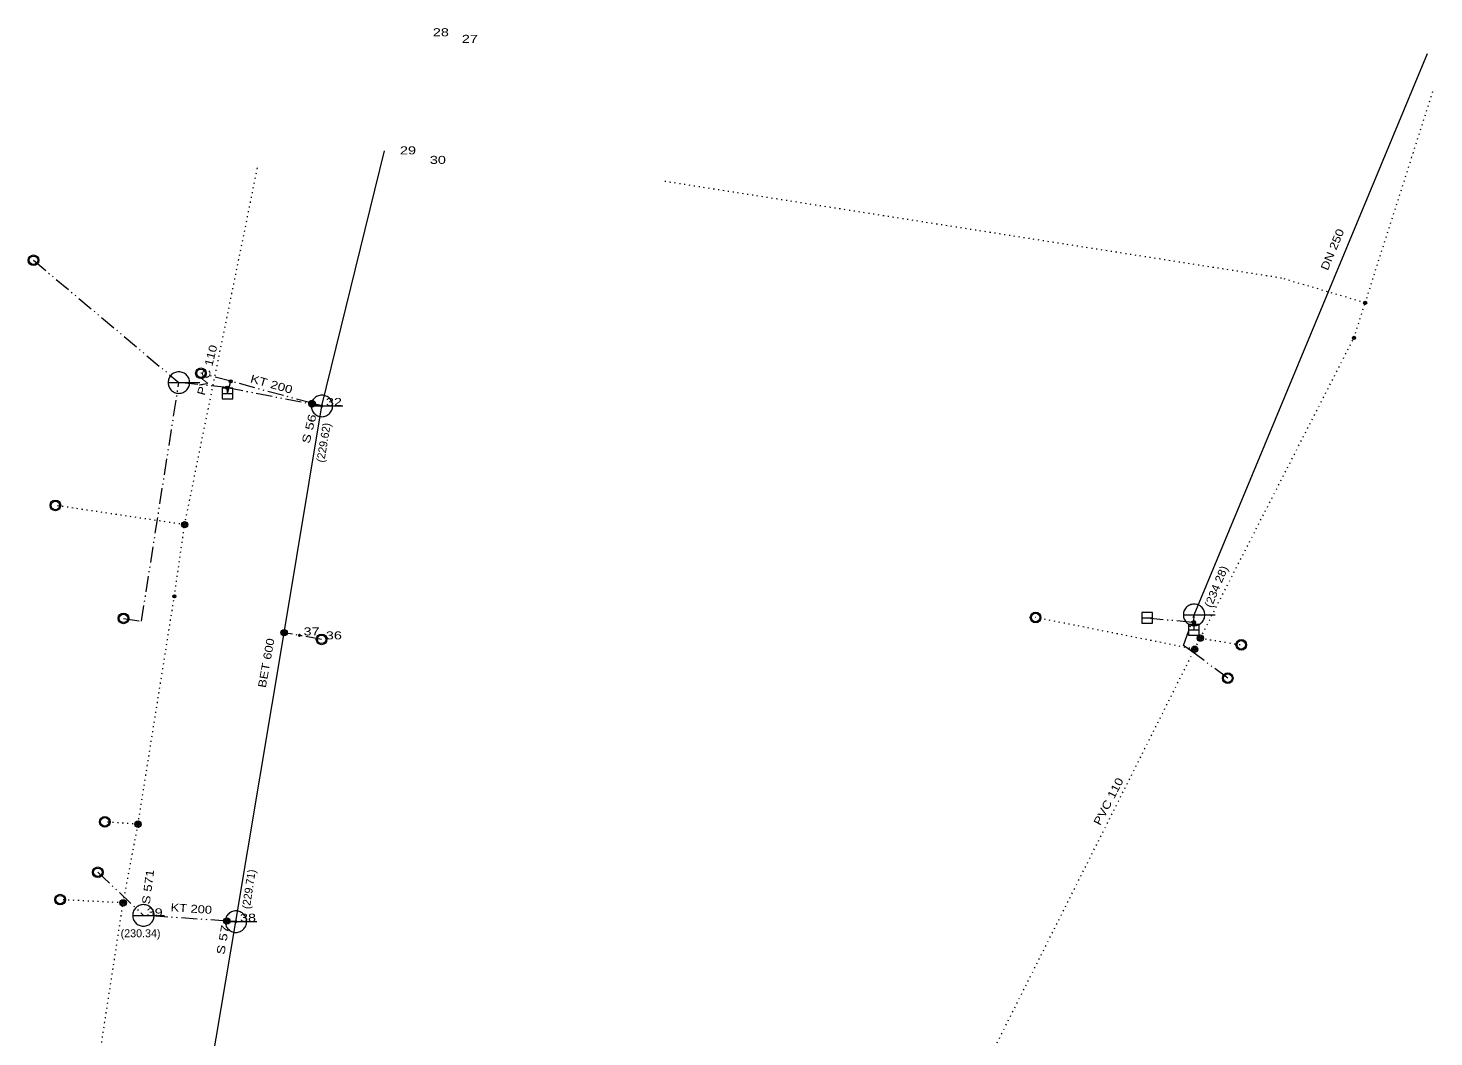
# Model space of a CAD drawing. Extents: x -648128 to -647962, y -1064951 to -1064761.
# Drawn here: x -648094.1 to -647962.3, y -1064855.2 to -1064760.6 of the extents above; entities that cross this region are included whole.
import ezdxf
from ezdxf.enums import TextEntityAlignment as Align

# ---------------------------------------------------------------- set-up
doc = ezdxf.new("R2010")
doc.units = 0
doc.header["$LTSCALE"] = 0.3
doc.header["$PDMODE"] = 32
doc.header["$PDSIZE"] = 0.15
doc.linetypes.add('DASH_DOUBLE_DOT', pattern=[9.2, 5, -1.2, 0.3, -1.2, 0.3, -1.2])
doc.linetypes.add('DOTTED', pattern=[1.5, 0.3, -1.2])
for name, color, linetype in [('1', 7, 'Continuous'), ('16', 7, 'Continuous'), ('18', 7, 'Continuous'), ('19', 7, 'Continuous'), ('2', 7, 'Continuous'), ('4', 7, 'Continuous')]:
    doc.layers.add(name, color=color, linetype=linetype)
for name, color, linetype, lineweight in [('10', 7, 'Continuous', 13), ('12', 7, 'Continuous', 13), ('30', 7, 'Continuous', 13), ('36', 7, 'DOTTED', 13), ('46', 7, 'Continuous', 13), ('5', 7, 'Continuous', 13), ('51', 7, 'DASH_DOUBLE_DOT', 13)]:
    doc.layers.add(name, color=color, linetype=linetype, lineweight=lineweight)

msp = doc.modelspace()

# ---------------------------------------------------------------- linework, layer by layer
at = {"layer": '1'}
for p in [(-648066.57, -1064796.08), (-648068.67, -1064817.6), (-648074.63, -1064844.44)]:
    msp.add_point(p, dxfattribs=at)
at = {"layer": '10'}
for p, q in [((-648075.92, -1064794.91), (-648074.92, -1064794.91)), ((-647989.7, -1064815.95), (-647988.7, -1064815.95)), ((-647985.35, -1064817.06), (-647984.35, -1064817.06))]:
    msp.add_line(p, q, dxfattribs=at)
for points in [[(-648075.92, -1064795.41), (-648074.92, -1064795.41), (-648074.92, -1064794.41), (-648075.92, -1064794.41)], [(-647989.7, -1064816.45), (-647988.7, -1064816.45), (-647988.7, -1064815.45), (-647989.7, -1064815.45)], [(-647985.35, -1064817.56), (-647984.35, -1064817.56), (-647984.35, -1064816.56), (-647985.35, -1064816.56)]]:
    msp.add_lwpolyline(points, close=True, dxfattribs=at)
at = {"layer": '12'}
for p, q in [((-648080.988, -1064793.89), (-648078.011, -1064793.89)), ((-648067.578, -1064796.08), (-648064.601, -1064796.08)), ((-647985.818, -1064815.67), (-647982.841, -1064815.67)), ((-648084.308, -1064843.85), (-648081.331, -1064843.85)), ((-648075.638, -1064844.44), (-648072.661, -1064844.44))]:
    msp.add_line(p, q, dxfattribs=at)
for points in [[(-648079.98, -1064792.882), (-648080.085, -1064792.888), (-648080.189, -1064792.904), (-648080.291, -1064792.931), (-648080.389, -1064792.969), (-648080.483, -1064793.017), (-648080.571, -1064793.074), (-648080.654, -1064793.141), (-648080.729, -1064793.216), (-648080.795, -1064793.298), (-648080.852, -1064793.385), (-648080.899, -1064793.48), (-648080.937, -1064793.579), (-648080.965, -1064793.68), (-648080.981, -1064793.785), (-648080.988, -1064793.89), (-648080.981, -1064793.995), (-648080.965, -1064794.1), (-648080.937, -1064794.202), (-648080.899, -1064794.3), (-648080.852, -1064794.393), (-648080.795, -1064794.483), (-648080.729, -1064794.565), (-648080.654, -1064794.639), (-648080.571, -1064794.705), (-648080.483, -1064794.763), (-648080.389, -1064794.811), (-648080.291, -1064794.849), (-648080.189, -1064794.876), (-648080.085, -1064794.892), (-648079.98, -1064794.898), (-648079.874, -1064794.892), (-648079.769, -1064794.876), (-648079.668, -1064794.849), (-648079.57, -1064794.811), (-648079.475, -1064794.763), (-648079.387, -1064794.705), (-648079.305, -1064794.639), (-648079.23, -1064794.565), (-648079.164, -1064794.483), (-648079.107, -1064794.393), (-648079.058, -1064794.3), (-648079.02, -1064794.202), (-648078.994, -1064794.1), (-648078.978, -1064793.995), (-648078.972, -1064793.89), (-648078.978, -1064793.785), (-648078.994, -1064793.68), (-648079.02, -1064793.579), (-648079.058, -1064793.48), (-648079.107, -1064793.385), (-648079.164, -1064793.298), (-648079.23, -1064793.216), (-648079.305, -1064793.141), (-648079.387, -1064793.074), (-648079.475, -1064793.017), (-648079.57, -1064792.969), (-648079.668, -1064792.931), (-648079.769, -1064792.904), (-648079.874, -1064792.888)], [(-648066.57, -1064795.072), (-648066.675, -1064795.078), (-648066.779, -1064795.094), (-648066.881, -1064795.121), (-648066.979, -1064795.159), (-648067.073, -1064795.207), (-648067.161, -1064795.264), (-648067.244, -1064795.331), (-648067.319, -1064795.406), (-648067.385, -1064795.488), (-648067.442, -1064795.575), (-648067.489, -1064795.67), (-648067.527, -1064795.769), (-648067.555, -1064795.87), (-648067.571, -1064795.975), (-648067.578, -1064796.08), (-648067.571, -1064796.185), (-648067.555, -1064796.29), (-648067.527, -1064796.392), (-648067.489, -1064796.49), (-648067.442, -1064796.583), (-648067.385, -1064796.673), (-648067.319, -1064796.755), (-648067.244, -1064796.829), (-648067.161, -1064796.895), (-648067.073, -1064796.953), (-648066.979, -1064797.001), (-648066.881, -1064797.039), (-648066.779, -1064797.066), (-648066.675, -1064797.082), (-648066.57, -1064797.088), (-648066.464, -1064797.082), (-648066.359, -1064797.066), (-648066.258, -1064797.039), (-648066.16, -1064797.001), (-648066.065, -1064796.953), (-648065.977, -1064796.895), (-648065.895, -1064796.829), (-648065.82, -1064796.755), (-648065.754, -1064796.673), (-648065.697, -1064796.583), (-648065.648, -1064796.49), (-648065.61, -1064796.392), (-648065.584, -1064796.29), (-648065.568, -1064796.185), (-648065.562, -1064796.08), (-648065.568, -1064795.975), (-648065.584, -1064795.87), (-648065.61, -1064795.769), (-648065.648, -1064795.67), (-648065.697, -1064795.575), (-648065.754, -1064795.488), (-648065.82, -1064795.406), (-648065.895, -1064795.331), (-648065.977, -1064795.264), (-648066.065, -1064795.207), (-648066.16, -1064795.159), (-648066.258, -1064795.121), (-648066.359, -1064795.094), (-648066.464, -1064795.078)], [(-647984.81, -1064814.662), (-647984.915, -1064814.668), (-647985.019, -1064814.684), (-647985.121, -1064814.711), (-647985.219, -1064814.749), (-647985.313, -1064814.797), (-647985.401, -1064814.854), (-647985.484, -1064814.921), (-647985.559, -1064814.996), (-647985.625, -1064815.078), (-647985.682, -1064815.165), (-647985.729, -1064815.26), (-647985.767, -1064815.359), (-647985.795, -1064815.46), (-647985.811, -1064815.565), (-647985.818, -1064815.67), (-647985.811, -1064815.775), (-647985.795, -1064815.88), (-647985.767, -1064815.982), (-647985.729, -1064816.08), (-647985.682, -1064816.173), (-647985.625, -1064816.263), (-647985.559, -1064816.345), (-647985.484, -1064816.419), (-647985.401, -1064816.485), (-647985.313, -1064816.543), (-647985.219, -1064816.591), (-647985.121, -1064816.629), (-647985.019, -1064816.656), (-647984.915, -1064816.672), (-647984.81, -1064816.678), (-647984.704, -1064816.672), (-647984.599, -1064816.656), (-647984.498, -1064816.629), (-647984.4, -1064816.591), (-647984.305, -1064816.543), (-647984.217, -1064816.485), (-647984.135, -1064816.419), (-647984.06, -1064816.345), (-647983.994, -1064816.263), (-647983.937, -1064816.173), (-647983.888, -1064816.08), (-647983.85, -1064815.982), (-647983.824, -1064815.88), (-647983.808, -1064815.775), (-647983.802, -1064815.67), (-647983.808, -1064815.565), (-647983.824, -1064815.46), (-647983.85, -1064815.359), (-647983.888, -1064815.26), (-647983.937, -1064815.165), (-647983.994, -1064815.078), (-647984.06, -1064814.996), (-647984.135, -1064814.921), (-647984.217, -1064814.854), (-647984.305, -1064814.797), (-647984.4, -1064814.749), (-647984.498, -1064814.711), (-647984.599, -1064814.684), (-647984.704, -1064814.668)], [(-648083.3, -1064842.842), (-648083.405, -1064842.848), (-648083.509, -1064842.864), (-648083.611, -1064842.891), (-648083.709, -1064842.929), (-648083.803, -1064842.977), (-648083.891, -1064843.034), (-648083.974, -1064843.101), (-648084.049, -1064843.176), (-648084.115, -1064843.258), (-648084.172, -1064843.345), (-648084.219, -1064843.44), (-648084.257, -1064843.539), (-648084.285, -1064843.64), (-648084.301, -1064843.745), (-648084.308, -1064843.85), (-648084.301, -1064843.955), (-648084.285, -1064844.06), (-648084.257, -1064844.162), (-648084.219, -1064844.26), (-648084.172, -1064844.353), (-648084.115, -1064844.443), (-648084.049, -1064844.525), (-648083.974, -1064844.599), (-648083.891, -1064844.665), (-648083.803, -1064844.723), (-648083.709, -1064844.771), (-648083.611, -1064844.809), (-648083.509, -1064844.836), (-648083.405, -1064844.852), (-648083.3, -1064844.858), (-648083.194, -1064844.852), (-648083.089, -1064844.836), (-648082.988, -1064844.809), (-648082.89, -1064844.771), (-648082.795, -1064844.723), (-648082.707, -1064844.665), (-648082.625, -1064844.599), (-648082.55, -1064844.525), (-648082.484, -1064844.443), (-648082.427, -1064844.353), (-648082.378, -1064844.26), (-648082.34, -1064844.162), (-648082.314, -1064844.06), (-648082.298, -1064843.955), (-648082.292, -1064843.85), (-648082.298, -1064843.745), (-648082.314, -1064843.64), (-648082.34, -1064843.539), (-648082.378, -1064843.44), (-648082.427, -1064843.345), (-648082.484, -1064843.258), (-648082.55, -1064843.176), (-648082.625, -1064843.101), (-648082.707, -1064843.034), (-648082.795, -1064842.977), (-648082.89, -1064842.929), (-648082.988, -1064842.891), (-648083.089, -1064842.864), (-648083.194, -1064842.848)], [(-648074.63, -1064843.432), (-648074.735, -1064843.438), (-648074.839, -1064843.454), (-648074.941, -1064843.481), (-648075.039, -1064843.519), (-648075.133, -1064843.567), (-648075.221, -1064843.624), (-648075.304, -1064843.691), (-648075.379, -1064843.766), (-648075.445, -1064843.848), (-648075.502, -1064843.935), (-648075.549, -1064844.03), (-648075.587, -1064844.129), (-648075.615, -1064844.23), (-648075.631, -1064844.335), (-648075.638, -1064844.44), (-648075.631, -1064844.545), (-648075.615, -1064844.65), (-648075.587, -1064844.752), (-648075.549, -1064844.85), (-648075.502, -1064844.943), (-648075.445, -1064845.033), (-648075.379, -1064845.115), (-648075.304, -1064845.189), (-648075.221, -1064845.255), (-648075.133, -1064845.313), (-648075.039, -1064845.361), (-648074.941, -1064845.399), (-648074.839, -1064845.426), (-648074.735, -1064845.442), (-648074.63, -1064845.448), (-648074.524, -1064845.442), (-648074.419, -1064845.426), (-648074.318, -1064845.399), (-648074.22, -1064845.361), (-648074.125, -1064845.313), (-648074.037, -1064845.255), (-648073.955, -1064845.189), (-648073.88, -1064845.115), (-648073.814, -1064845.033), (-648073.757, -1064844.943), (-648073.708, -1064844.85), (-648073.67, -1064844.752), (-648073.644, -1064844.65), (-648073.628, -1064844.545), (-648073.622, -1064844.44), (-648073.628, -1064844.335), (-648073.644, -1064844.23), (-648073.67, -1064844.129), (-648073.708, -1064844.03), (-648073.757, -1064843.935), (-648073.814, -1064843.848), (-648073.88, -1064843.766), (-648073.955, -1064843.691), (-648074.037, -1064843.624), (-648074.125, -1064843.567), (-648074.22, -1064843.519), (-648074.318, -1064843.481), (-648074.419, -1064843.454), (-648074.524, -1064843.438)]]:
    msp.add_lwpolyline(points, close=True, dxfattribs=at)
at = {"layer": '30'}
for centre, radius in [((-648093.61, -1064782.42), 0.5), ((-648093.61, -1064782.42), 0.4), ((-648077.908, -1064793.019), 0.5), ((-648077.908, -1064793.019), 0.4), ((-648075.45, -1064794.36), 0.15), ((-648075.45, -1064794.36), 0.075), ((-648075.117, -1064793.772), 0.15), ((-648075.117, -1064793.772), 0.075), ((-648067.4936, -1064795.8306), 0.3), ((-648067.4909, -1064795.9016), 0.3), ((-648067.4936, -1064795.8306), 0.2), ((-648067.4909, -1064795.9016), 0.2), ((-648067.4936, -1064795.8306), 0.1), ((-648067.4909, -1064795.9016), 0.1), ((-648085.17, -1064816), 0.5), ((-648085.17, -1064816), 0.4), ((-648070.114, -1064817.344), 0.3), ((-648070.114, -1064817.344), 0.2), ((-648070.114, -1064817.344), 0.1), ((-647984.83, -1064816.364), 0.15), ((-647984.83, -1064816.364), 0.075), ((-648066.597, -1064817.967), 0.5), ((-648066.597, -1064817.967), 0.4), ((-647981.657, -1064821.612), 0.5), ((-647981.657, -1064821.612), 0.4), ((-648087.58, -1064839.81), 0.5), ((-648087.58, -1064839.81), 0.4), ((-648075.4755, -1064844.3825), 0.3), ((-648075.4755, -1064844.3825), 0.2), ((-648075.4755, -1064844.3825), 0.1)]:
    msp.add_circle(centre, radius, dxfattribs=at)
at = {"layer": '36'}
for p, q in [((-647968.773, -1064786.412), (-647962.334, -1064766.291)), ((-648079.438, -1064807.217), (-648072.609, -1064773.76)), ((-647969.824, -1064789.697), (-647968.773, -1064786.412)), ((-647984.231, -1064817.849), (-647969.824, -1064789.697)), ((-648080.4, -1064813.93), (-648079.438, -1064807.217)), ((-648083.807, -1064835.297), (-648080.4, -1064813.93)), ((-647984.756, -1064818.896), (-647984.231, -1064817.849)), ((-648004.096, -1064857.445), (-647984.756, -1064818.896)), ((-648085.203, -1064842.68), (-648083.807, -1064835.297)), ((-648088.822, -1064866.224), (-648085.203, -1064842.68))]:
    msp.add_line(p, q, dxfattribs=at)
msp.add_lwpolyline([(-647968.773, -1064786.412), (-647976.614, -1064784.098), (-648034.493, -1064775.019)], dxfattribs=at)
at = {"layer": '46'}
for p, q in [((-647984.81, -1064815.67), (-647962.943, -1064763.04)), ((-648066.57, -1064796.08), (-648060.709, -1064772.147)), ((-648070.114, -1064817.344), (-648066.57, -1064796.08)), ((-648074.63, -1064844.44), (-648070.114, -1064817.344)), ((-648083.14, -1064894.9), (-648074.63, -1064844.44))]:
    msp.add_line(p, q, dxfattribs=at)
at = {"layer": '5'}
for centre, radius in [((-647968.773, -1064786.412), 0.15), ((-647968.773, -1064786.412), 0.075), ((-647969.824, -1064789.697), 0.15), ((-647969.824, -1064789.697), 0.075), ((-648091.557, -1064805.407), 0.5), ((-648091.557, -1064805.407), 0.4), ((-648079.438, -1064807.217), 0.3), ((-648079.438, -1064807.217), 0.2), ((-648079.438, -1064807.217), 0.1), ((-648080.4, -1064813.93), 0.15), ((-648080.4, -1064813.93), 0.075), ((-647999.665, -1064815.92), 0.5), ((-647999.665, -1064815.92), 0.4), ((-647984.756, -1064818.896), 0.3), ((-647984.231, -1064817.849), 0.3), ((-647984.231, -1064817.849), 0.2), ((-647984.231, -1064817.849), 0.1), ((-647980.388, -1064818.483), 0.5), ((-647980.388, -1064818.483), 0.4), ((-647984.756, -1064818.896), 0.2), ((-647984.756, -1064818.896), 0.1), ((-648086.92, -1064835.085), 0.5), ((-648086.92, -1064835.085), 0.4), ((-648083.807, -1064835.297), 0.3), ((-648083.807, -1064835.297), 0.2), ((-648083.807, -1064835.297), 0.1), ((-648091.104, -1064842.375), 0.5), ((-648091.104, -1064842.375), 0.4), ((-648085.203, -1064842.68), 0.3), ((-648085.203, -1064842.68), 0.2), ((-648085.203, -1064842.68), 0.1)]:
    msp.add_circle(centre, radius, dxfattribs=at)
at = {"layer": '51'}
for p, q in [((-648093.61, -1064782.42), (-648079.98, -1064793.89)), ((-648075.117, -1064793.772), (-648077.908, -1064793.019)), ((-648075.45, -1064794.36), (-648079.98, -1064793.89)), ((-648075.42, -1064794.91), (-648075.117, -1064793.772)), ((-648067.494, -1064795.831), (-648075.117, -1064793.772)), ((-648066.57, -1064796.08), (-648067.494, -1064795.831)), ((-648067.491, -1064795.902), (-648066.57, -1064796.08)), ((-647989.2, -1064815.95), (-647984.83, -1064816.364)), ((-647984.83, -1064816.364), (-647984.81, -1064815.67)), ((-647984.83, -1064816.364), (-647984.85, -1064817.06)), ((-648066.597, -1064817.967), (-648070.114, -1064817.344)), ((-648087.58, -1064839.81), (-648083.3, -1064843.85)), ((-648075.475, -1064844.382), (-648083.3, -1064843.85)), ((-648074.63, -1064844.44), (-648075.475, -1064844.382))]:
    msp.add_line(p, q, dxfattribs=at)
at = {"layer": '51', "linetype": 'DOTTED'}
for p, q in [((-648079.438, -1064807.217), (-648091.557, -1064805.407)), ((-647984.756, -1064818.896), (-647999.665, -1064815.92)), ((-647984.231, -1064817.849), (-647980.388, -1064818.483)), ((-648083.807, -1064835.297), (-648086.92, -1064835.085)), ((-648085.203, -1064842.68), (-648091.104, -1064842.375))]:
    msp.add_line(p, q, dxfattribs=at)
at = {"layer": '51'}
for points in [[(-648085.17, -1064816), (-648083.48, -1064816.26), (-648079.98, -1064793.89)], [(-648075.42, -1064794.91), (-648075.45, -1064794.36), (-648067.491, -1064795.902)], [(-647981.657, -1064821.612), (-647984.6, -1064819.41), (-647985.8, -1064818.54), (-647984.81, -1064815.67)]]:
    msp.add_lwpolyline(points, dxfattribs=at)

# ---------------------------------------------------------------- texts
at = {"layer": '16', "width": 1.2}
for rotation, p in [(75.615, (-648076.959, -1064792.8057)), (62.604, (-647992.5063, -1064833.3381))]:
    msp.add_text('PVC 110', height=0.75, rotation=rotation, dxfattribs=at).set_placement(p, align=Align.CENTER)
at = {"layer": '18'}
for s, rotation, width, p in [('DN 250', 67.438, 1.2, (-647971.5011, -1064781.5519)), ('S 56', 76.239, 1.35, (-648067.408, -1064798.3077)), ('BET 600', 79.741, 1.2, (-648071.4197, -1064820.2493)), ('S 571', 82.598, 1.25, (-648082.499, -1064841.2248)), ('S 57', 80.427, 1.35, (-648075.4862, -1064846.2054))]:
    msp.add_text(s, height=0.75, rotation=rotation, dxfattribs=dict(at, width=width)).set_placement(p, align=Align.CENTER)
at = {"layer": '19'}
for rotation, width, p in [(344.325, 1.25, (-648071.3953, -1064794.3953)), (356.232, 1.2, (-648078.8341, -1064843.5887))]:
    msp.add_text('KT 200', height=0.75, rotation=rotation, dxfattribs=dict(at, width=width)).set_placement(p, align=Align.CENTER)
at = {"layer": '2', "width": 1.35}
for s, p in [(' 28', (-648056.55, -1064761.41)), (' 27', (-648053.83, -1064762.03)), (' 29', (-648059.63, -1064772.49)), (' 30', (-648056.83, -1064773.38)), (' 32', (-648066.57, -1064796.08)), (' 37', (-648068.67, -1064817.6)), (' 36', (-648066.58, -1064817.97)), (' 39', (-648083.38, -1064843.94)), (' 38', (-648074.63, -1064844.44))]:
    msp.add_text(s, height=0.75, dxfattribs=at).set_placement(p)
at = {"layer": '4'}
for s, rotation, p in [('(229.62)', 80.476, (-648066.353, -1064801.42)), ('(229.71)', 81.422, (-648073.327, -1064843.295))]:
    msp.add_text(s, height=0.75, rotation=rotation, dxfattribs=at).set_placement(p)
at = {"layer": '4', "width": 1.1}
msp.add_text('(234 28)', height=0.75, rotation=67.574, dxfattribs=at).set_placement((-647983.179, -1064815.062))
at = {"layer": '4'}
msp.add_text('(230.34)', height=0.75, dxfattribs=at).set_placement((-648085.437, -1064845.904))

doc.saveas('drawing.dxf')
